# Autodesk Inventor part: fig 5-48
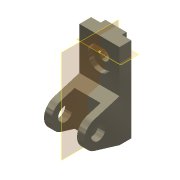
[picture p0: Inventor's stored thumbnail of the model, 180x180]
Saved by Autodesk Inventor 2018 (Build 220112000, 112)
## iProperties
Shininess: 65.0
Angle Display Precision: 2
Document Length Units: 11269
Document Angle Units: 11279
Document Time Units: 11290
Document Mass Units: 11283
Document Length Units Precision: 3
Document Angle Units Precision: 2
Created: 2001-11
Part Number: fig 5-48
Document SubType Name: Modeling
Designer: Renu Muthoo
Density: 1 g/cm^3
Material: Generic
Appearance: Metal-Titanium (Polished)
Density: 0.0
Volumn: 0.0
Area: 0.0
PropertySet Name: Model Information
Control State: 0
Master: False
Checked Out: False
Author: Renu Muthoo
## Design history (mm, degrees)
node "Sketch1"
sketch "Sketch2"
  geometry: L1 (33.257, 104.664)-(33.257, -75.336); L2 (33.257, -75.336)-(8.257, -75.336); L3 (8.257, -75.336)-(-45.451, -59.045); L4 (-45.451, -1.628)-(8.257, 14.664); L5 (8.257, 14.664)-(8.257, 104.664); L6 (8.257, 104.664)-(33.257, 104.664); C1 r 15 at (-36.743, -30.336); A1 r 30 centre (-36.743, -30.336) between (-45.451, -1.628) and (-45.451, -59.045)
  constraints: 12 end point, 2 centre point, 2 equal length, 2 parallel, 2 point on circle, 2 tangent, 1 coincident, 1 perpendicular, 1 vertical
  dimensions: "d0" = 180 distance of L1.start L1.end; "d1" = 30 radius of A1; "d2" = 25 distance of L5.end L1.start; "d3" = 45 distance from line of L2 A1.centre; "d4" = 70 distance from line of L1 A1.centre; "d5" = 30 diameter of C1
extrude "Extrusion1" new body sketch "Sketch2" distance "d6" = 85; taper "d7" = 0 deg
workplane "Work Plane1"
sketch "Sketch3"
  geometry: L1 (15, 62.364)-(70, 62.364); L2 (70, 62.364)-(70, -52.386); L3 (70, -52.386)-(15, -52.386); L4 (15, -52.386)-(15, 62.364); L5 (0, -45)-(0, -28.708) reference
  constraints: 8 end point, 2 parallel, 1 horizontal, 1 perpendicular
  dimensions: "d8" = 55 distance of L1.start L1.end; "d9" = 15 distance between parallel lines of L5 L4
extrude "Extrusion2" cut sketch "Sketch3" distance "d10" = 50; taper "d11" = 0 deg
sketch "Sketch4"
  geometry: L1 (0, 25)-(85, 25) reference; L2 (0, 0)-(0, 25) reference; L3 (20, 25)-(65, 25); L4 (65, 25)-(65, 35); L5 (65, 35)-(20, 35); L6 (20, 35)-(20, 25)
  constraints: 8 end point, 2 parallel, 1 horizontal, 1 perpendicular, 1 point on line
  dimensions: "d12" = 45 distance of L4.end L5.end; "d13" = 10 distance of L3.end L4.end; "d14" = 20 distance between parallel lines of L2 L6
extrude "Extrusion3" join sketch "Sketch4" stored distance "d15" = 50; taper "d16" = 0 deg
sketch "Sketch5"
  geometry: L1 (85, 0)-(85, 90) reference; L2 (0, 90)-(85, 90) reference; 1 further point
  dimensions: "d17" = 42 distance from line of L2 point (42.5, 48); "d18" = 42.5 distance from line of L1 point (42.5, 48)
hole "Hole1" sketch "Sketch5" at (42.5, 48) diameter "d19" = 20; stored, may be unused: countersink angle "d23" = 82 deg, drill point angle "d25" = 118 deg; dims "d20" = 6, "d21" = 50, "d22" = 10, "d24" = 8
workpoint "Work Point9"
  workplane "Work Plane8"
  workplane "Work Plane12"
body "Solid1"
